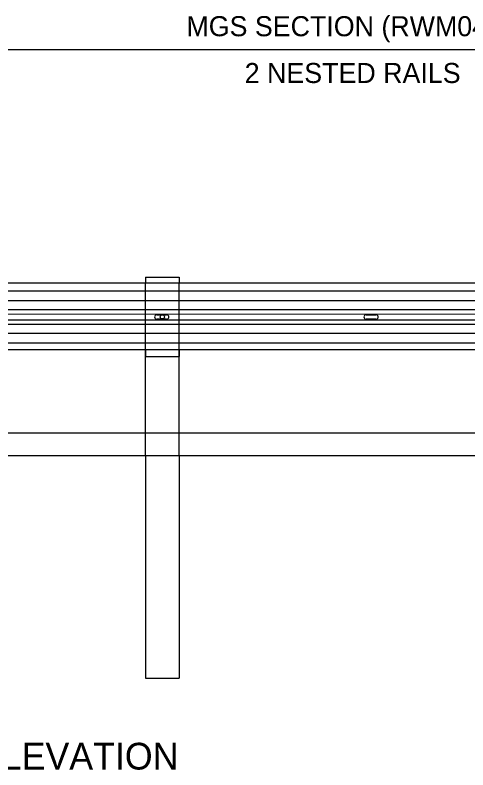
# Model space of a CAD drawing. Extents: x 49991 to 50160, y 49948 to 50051.
# Drawn here: x 50005.881 to 50007.237, y 49994.044 to 49996.303 of the extents above; entities that cross this region are included whole.
import ezdxf

# ---------------------------------------------------------------- set-up
doc = ezdxf.new("R2010")
doc.units = 0
for name, color, linetype in [('Level 1', 7, 'Continuous'), ('Level 2', 7, 'Continuous'), ('Level 3', 7, 'Continuous'), ('Level 4', 7, 'Continuous')]:
    doc.layers.add(name, color=color, linetype=linetype)

msp = doc.modelspace()

# ---------------------------------------------------------------- linework, layer by layer
at = {"layer": 'Level 1'}
for p, q in [((50004.3866, 49995.5019), (50011.6716, 49995.5014)), ((50006.2716, 49995.5184), (50006.2716, 49995.5018)), ((50006.2716, 49995.5184), (50006.3716, 49995.5184)), ((50006.2716, 49995.5184), (50006.2716, 49995.5018)), ((50006.2716, 49995.5184), (50006.3716, 49995.5184)), ((50006.3716, 49995.5184), (50006.3716, 49995.5017)), ((50006.3716, 49995.5184), (50006.3716, 49995.5018)), ((50004.5497, 49995.4776), (50011.6716, 49995.4776)), ((50004.5497, 49995.4485), (50011.6716, 49995.4479)), ((50004.5497, 49995.4214), (50011.6716, 49995.4224)), ((50005.0854, 49995.4089), (50011.6716, 49995.4067)), ((50011.6716, 49995.3901), (50005.5897, 49995.3902)), ((50006.305, 49995.4059), (50006.3345, 49995.4059)), ((50006.3345, 49995.3928), (50006.305, 49995.3928)), ((50006.9319, 49995.4059), (50006.9614, 49995.4059)), ((50006.9614, 49995.3928), (50006.9319, 49995.3928)), ((50011.6716, 49995.3772), (50005.5897, 49995.3772)), ((50011.6716, 49995.3503), (50005.5897, 49995.3503)), ((50011.6716, 49995.3213), (50005.5897, 49995.3213)), ((50011.6716, 49995.3011), (50005.5897, 49995.3011)), ((50006.2716, 49995.0517), (50006.2716, 49995.3011)), ((50006.2716, 49995.3011), (50006.2716, 49995.2809)), ((50006.3716, 49995.0516), (50006.3716, 49995.3011)), ((50006.3716, 49995.3011), (50006.3716, 49995.2809)), ((50006.2716, 49995.2809), (50006.3716, 49995.2809)), ((50011.6716, 49995.0514), (50000.8008, 49995.0519)), ((49999.8072, 49994.9853), (50011.6716, 49994.9848))]:
    msp.add_line(p, q, dxfattribs=at)
msp.add_circle((50006.3216, 49995.3997), 0.00625, dxfattribs=at)
for centre, start, end in [((50006.305, 49995.3994), 90, 270), ((50006.3345, 49995.3994), 270, 90), ((50006.9319, 49995.3994), 90, 270), ((50006.9614, 49995.3994), 270, 90)]:
    msp.add_arc(centre, 0.00656, start, end, dxfattribs=at)
at = {"layer": 'Level 3'}
msp.add_line((50005.6966, 49996.1994), (50008.1966, 49996.1994), dxfattribs=at)
at = {"layer": 'Level 4'}
for p, q in [((50006.2716, 49995.3011), (50006.2716, 49995.5019)), ((50006.2716, 49995.3011), (50006.2716, 49995.5018)), ((50006.3716, 49995.3011), (50006.3716, 49995.5019)), ((50006.3716, 49995.3011), (50006.3716, 49995.5018)), ((50006.2716, 49994.985), (50006.2716, 49995.0517)), ((50006.3716, 49994.985), (50006.3716, 49995.0516)), ((50006.2716, 49994.9851), (50006.2716, 49994.3184)), ((50006.3716, 49994.9851), (50006.3716, 49994.3184)), ((50006.2716, 49994.3184), (50006.3716, 49994.3184))]:
    msp.add_line(p, q, dxfattribs=at)

# ---------------------------------------------------------------- texts
at = {"layer": 'Level 2'}
for s, height, p in [('MGS SECTION (RWM04a*)', 0.06, (50006.3937, 49996.2394)), ('2 NESTED RAILS', 0.06, (50006.5682, 49996.0994)), ('ELEVATION', 0.08, (50005.7693, 49994.0455))]:
    msp.add_text(s, height=height, dxfattribs=at).set_placement(p)

doc.saveas('drawing.dxf')
